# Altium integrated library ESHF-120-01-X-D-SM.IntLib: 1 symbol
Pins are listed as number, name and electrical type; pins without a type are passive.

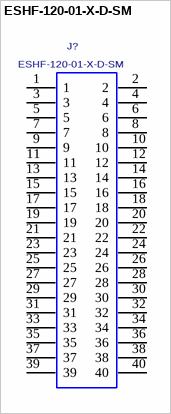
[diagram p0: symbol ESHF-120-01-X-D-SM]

## ESHF-120-01-X-D-SM
designator J?
0.05"X0.05" SHROUDED TERMINAL STRIP, 40 PINS.; MANUFACTURER: SAMTEC
footprint ESHF-120-01-X-D-SM
pins: 1, 2, 3, 4, 5, 6, 7, 8, 9, 10, 11, 12, 13, 14, 15, 16, 17, 18, 19, 20, 21, 22, 23, 24, 25, 26, 27, 28, 29, 30, 31, 32, 33, 34, 35, 36, 37, 38, 39, 40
